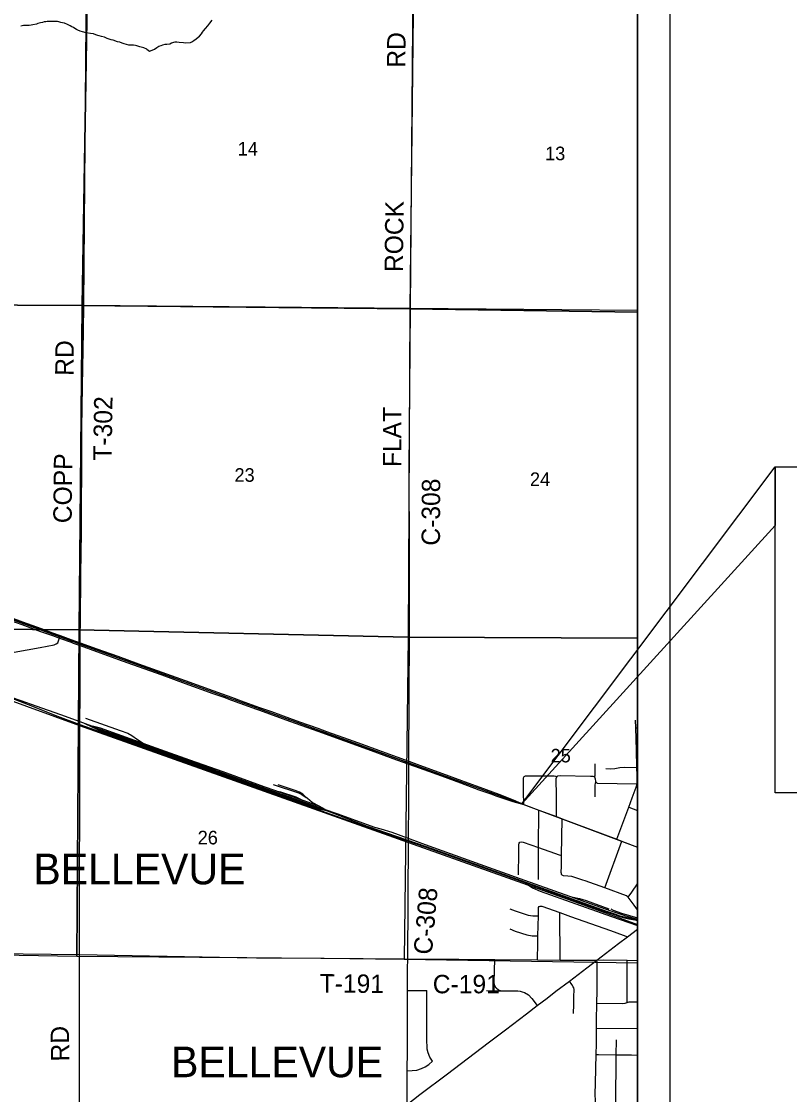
# Model space of a CAD drawing. Extents: x 0 to 34, y 0 to 22.
# Drawn here: x 6.998 to 9.369, y 14.74 to 18.051 of the extents above; entities that cross this region are included whole.
import ezdxf

# ---------------------------------------------------------------- set-up
doc = ezdxf.new("R2010")
doc.units = 0
for name, color, linetype in [('Default', 7, 'Continuous'), ('GM_X_City_Street', 7, 'Continuous'), ('GM_X_Corporation_Text', 7, 'Continuous'), ('GM_X_County_Road', 7, 'Continuous'), ('GM_X_County_Road_Text', 7, 'Continuous'), ('GM_X_Minor_River', 7, 'Continuous'), ('GM_X_Rail_Line', 7, 'Continuous'), ('GM_X_Section', 7, 'Continuous'), ('GM_X_Section_Text', 7, 'Continuous'), ('GM_X_State_Route', 7, 'Continuous'), ('GM_X_Township_Road', 7, 'Continuous'), ('GM_X_Township_Road_Text', 7, 'Continuous'), ('GM_X_US_Route', 7, 'Continuous'), ('SH_Cut_Line', 7, 'Continuous'), ('SH_Data', 7, 'Continuous'), ('SH_Text', 7, 'Continuous')]:
    doc.layers.add(name, color=color, linetype=linetype)

msp = doc.modelspace()

# ---------------------------------------------------------------- linework, layer by layer
at = {"layer": 'Default'}
for points in [[(8.9, 17.1539), (8.9, 18.1619), (8.2084, 18.1673), (8.1974, 17.1648)], [(8.9, 16.1483), (8.9, 17.1539), (8.1974, 17.1648), (8.192, 16.151)], [(8.9, 15.1461), (8.9, 16.1483), (8.192, 16.151), (8.1799, 15.1573)]]:
    msp.add_lwpolyline(points, close=True, dxfattribs=at)
msp.add_lwpolyline([(3.8857, 17.3198), (5.25, 16.8357), (6.6044, 16.3383), (8.5432, 15.6366)], dxfattribs=at)
at = {"layer": 'GM_X_City_Street'}
for p, q in [((8.8943, 15.8713), (8.9, 15.8712)), ((8.8966, 15.8026), (8.9, 15.8026)), ((8.8727, 15.6265), (8.9, 15.6164)), ((8.7988, 15.3772), (8.8517, 15.5218)), ((8.6609, 15.1547), (8.6602, 15.3011)), ((8.8676, 15.0241), (8.8681, 15.1541)), ((8.1903, 15.061), (8.2493, 15.0609)), ((8.7735, 14.9445), (8.9, 14.9432))]:
    msp.add_line(p, q, dxfattribs=at)
for points in [[(8.8358, 15.5278), (8.8727, 15.6265), (8.8832, 15.6557), (8.8956, 15.6887), (8.8992, 15.6989), (8.8986, 15.7256), (8.8978, 15.7492), (8.8966, 15.8026), (8.8943, 15.8713), (8.8933, 15.8951)], [(8.7669, 15.7202), (8.7688, 15.723), (8.7692, 15.7326), (8.7689, 15.7603)], [(8.802, 15.7463), (8.8157, 15.7453), (8.8301, 15.7464), (8.8457, 15.7493), (8.8587, 15.7499), (8.8978, 15.7492)], [(8.5487, 15.6345), (8.5482, 15.6753), (8.5483, 15.7172), (8.5504, 15.7214)], [(8.5504, 15.7214), (8.5537, 15.723), (8.5898, 15.7231), (8.6431, 15.7237), (8.6477, 15.7224), (8.6507, 15.7203)], [(8.7693, 15.6586), (8.7695, 15.6941), (8.7702, 15.7002), (8.772, 15.7032)], [(8.5943, 15.4029), (8.5944, 15.5018), (8.5954, 15.6174)], [(8.5326, 15.4176), (8.5336, 15.4859), (8.5335, 15.5105), (8.5348, 15.5158), (8.5369, 15.5184)], [(8.5369, 15.5184), (8.5409, 15.5195), (8.5474, 15.5183), (8.5944, 15.5018), (8.6438, 15.4841), (8.6578, 15.479), (8.6651, 15.4772)], [(8.871, 15.3489), (8.8824, 15.3647), (8.9, 15.3898)], [(8.5062, 15.3127), (8.5222, 15.3065), (8.5619, 15.2931), (8.5771, 15.291), (8.5939, 15.2908)], [(8.5909, 15.1554), (8.5921, 15.2065), (8.5924, 15.2296), (8.5939, 15.2908), (8.5941, 15.3128), (8.5947, 15.3173), (8.5967, 15.3199)], [(8.5967, 15.3199), (8.5998, 15.3211), (8.6042, 15.3208), (8.6602, 15.3011), (8.6926, 15.2896), (8.8168, 15.2456), (8.856, 15.2318), (8.8691, 15.2263)], [(8.8177, 15.3125), (8.8249, 15.3084), (8.8507, 15.2995), (8.9, 15.2847)], [(8.5062, 15.2512), (8.5227, 15.2443), (8.5582, 15.2321), (8.5743, 15.2297), (8.5924, 15.2296)], [(8.4772, 15.0597), (8.4703, 15.062), (8.4633, 15.0684), (8.4587, 15.0767), (8.4576, 15.0873), (8.4594, 15.1567)], [(8.7026, 14.9897), (8.7028, 15.0178), (8.7029, 15.041), (8.7039, 15.0642), (8.7032, 15.0686), (8.7016, 15.0725), (8.6968, 15.0791), (8.6897, 15.0897)], [(8.2675, 14.8425), (8.259, 14.8546), (8.2533, 14.8681), (8.2502, 14.88), (8.2495, 14.9122), (8.2496, 14.9707), (8.2496, 15.033), (8.2493, 15.0609)], [(8.4338, 15.0603), (8.4654, 15.06), (8.4772, 15.0597), (8.497, 15.0601), (8.5301, 15.0596), (8.5376, 15.0585), (8.5437, 15.0569), (8.5506, 15.0543), (8.5632, 15.0471), (8.5741, 15.0362), (8.5905, 15.0149)], [(8.7747, 15.0214), (8.8547, 15.0203), (8.8619, 15.0216), (8.8676, 15.0241), (8.8741, 15.0256), (8.9, 15.0253)], [(8.8329, 14.7098), (8.8343, 14.8612), (8.8347, 14.9085)], [(8.1893, 14.8132), (8.2038, 14.8136), (8.2184, 14.8152), (8.2333, 14.8197), (8.2446, 14.8254), (8.2557, 14.8328), (8.2675, 14.8425)], [(8.7498, 14.6428), (8.7497, 14.6531), (8.7522, 14.6595), (8.7593, 14.6674), (8.7668, 14.6745), (8.7695, 14.6791), (8.7705, 14.6844), (8.7699, 14.7085), (8.7727, 14.711), (8.7699, 14.7167), (8.7696, 14.7443), (8.7702, 14.7718), (8.7713, 14.8223), (8.7727, 14.8619)]]:
    msp.add_lwpolyline(points, dxfattribs=at)
at = {"layer": 'GM_X_County_Road'}
for p, q in [((8.1954, 16.6674), (8.1995, 17.1669)), ((8.1942, 15.8381), (8.1944, 15.8584)), ((8.1939, 15.7595), (8.1939, 15.7683)), ((8.1939, 15.7497), (8.1939, 15.7595)), ((8.1938, 15.6911), (8.1937, 15.7008)), ((8.1936, 15.6137), (8.1938, 15.6427)), ((8.1912, 15.2255), (8.1913, 15.2351)), ((8.1905, 15.1577), (8.1907, 15.1771)), ((8.1902, 15.1285), (8.1905, 15.1577)), ((8.1905, 15.1577), (8.2102, 15.1577)), ((8.2102, 15.1577), (8.2792, 15.1577)), ((8.3089, 15.1577), (8.3485, 15.1574)), ((8.3485, 15.1574), (8.4376, 15.1568))]:
    msp.add_line(p, q, dxfattribs=at)
for points in [[(8.1995, 17.1669), (8.2077, 18.164), (8.2125, 18.6542), (8.228, 19.2286), (8.2296, 19.6352)], [(8.196, 16.4172), (8.1954, 16.6624), (8.1954, 16.6674)], [(8.1961, 16.2073), (8.1961, 16.2083), (8.1963, 16.2687), (8.196, 16.4122), (8.196, 16.4172)], [(8.1944, 15.8584), (8.1945, 15.8736), (8.1948, 15.9166), (8.1961, 16.2073)], [(8.194, 15.808), (8.1941, 15.8228), (8.1942, 15.8381)], [(8.1939, 15.7683), (8.1939, 15.7872), (8.194, 15.808)], [(8.1937, 15.7008), (8.1937, 15.7027), (8.1939, 15.7497)], [(8.6495, 15.5975), (8.6494, 15.6591), (8.649, 15.7158), (8.6494, 15.7167)], [(8.6494, 15.7167), (8.6507, 15.7203), (8.6542, 15.7228), (8.6616, 15.7238), (8.7546, 15.7225), (8.7618, 15.7218), (8.7649, 15.7208)], [(8.7649, 15.7208), (8.7669, 15.7202), (8.7692, 15.7143), (8.77, 15.7061), (8.772, 15.7032)], [(8.772, 15.7032), (8.7758, 15.701), (8.8992, 15.6989), (8.9, 15.6989)], [(8.1938, 15.6427), (8.1939, 15.6514), (8.1938, 15.6911)], [(8.1929, 15.5364), (8.1932, 15.5596), (8.1936, 15.6127), (8.1936, 15.6137)], [(8.6649, 15.4219), (8.6644, 15.4248), (8.6653, 15.4445), (8.6651, 15.4772), (8.6674, 15.591)], [(8.1926, 15.4977), (8.1926, 15.5064), (8.1929, 15.5364)], [(8.1924, 15.3713), (8.1924, 15.4022), (8.1926, 15.4687)], [(8.1926, 15.4687), (8.1926, 15.4716), (8.1926, 15.4977)], [(8.7381, 15.3989), (8.7316, 15.4013), (8.7062, 15.4099), (8.6973, 15.4126), (8.6852, 15.4138), (8.671, 15.4144), (8.6672, 15.4162), (8.6654, 15.419), (8.6649, 15.4219)], [(8.1921, 15.3324), (8.1924, 15.3616), (8.1924, 15.3713)], [(8.9, 15.3101), (8.8894, 15.3238), (8.871, 15.3489), (8.8658, 15.353), (8.7988, 15.3772), (8.7381, 15.3989)], [(8.1913, 15.2351), (8.1915, 15.2583), (8.1921, 15.3324)], [(8.1907, 15.1771), (8.1909, 15.1984), (8.1912, 15.2255)], [(8.2792, 15.1577), (8.299, 15.1577), (8.3089, 15.1577)], [(8.4376, 15.1568), (8.4594, 15.1567), (8.5909, 15.1554), (8.6609, 15.1547), (8.7747, 15.1546)], [(8.7796, 14.8618), (8.7727, 14.8619), (8.7731, 14.8969), (8.7735, 14.9445), (8.7737, 14.9683), (8.7747, 15.0214), (8.775, 15.0601), (8.7753, 15.1185), (8.7756, 15.1468), (8.7747, 15.1546)], [(8.7747, 15.1546), (8.7953, 15.1552), (8.8681, 15.1541), (8.9, 15.1535)], [(8.1888, 14.7087), (8.1891, 14.766), (8.1893, 14.8132), (8.1894, 14.8752), (8.1898, 14.9491), (8.1903, 15.061), (8.1901, 15.1198), (8.1902, 15.1285)], [(8.9, 14.8605), (8.8813, 14.8607), (8.8343, 14.8612), (8.7796, 14.8618)]]:
    msp.add_lwpolyline(points, dxfattribs=at)
at = {"layer": 'GM_X_Minor_River'}
for points in [[(7.3854, 17.9657), (7.3756, 17.9699), (7.3634, 17.9736), (7.3543, 17.9766), (7.3497, 17.9773), (7.344, 17.9781), (7.338, 17.9784), (7.33, 17.9784), (7.3224, 17.9799), (7.3156, 17.9821), (7.3091, 17.9847), (7.3015, 17.9874), (7.295, 17.9889), (7.2813, 17.9933), (7.2749, 17.9952), (7.2684, 17.9967), (7.2627, 17.9986), (7.2581, 18.0008), (7.254, 18.0027), (7.2448, 18.0049), (7.2384, 18.0072), (7.2338, 18.0083), (7.2281, 18.0106), (7.2205, 18.0128), (7.2114, 18.0143), (7.1981, 18.0169), (7.1863, 18.0199), (7.1795, 18.0217), (7.1722, 18.0244), (7.1681, 18.0262), (7.1627, 18.0296), (7.1585, 18.0326), (7.1536, 18.0353), (7.1483, 18.0375), (7.1403, 18.0421), (7.1311, 18.0466), (7.1251, 18.0473), (7.1201, 18.0488), (7.114, 18.0507), (7.1095, 18.0514), (7.0878, 18.0513), (7.0829, 18.0509), (7.078, 18.0513), (7.0734, 18.0508), (7.0685, 18.0501), (7.0632, 18.0485), (7.0571, 18.047), (7.0488, 18.045), (7.0442, 18.0435), (7.0336, 18.0415), (7.0279, 18.04), (7.0222, 18.0392), (7.0112, 18.0392), (7.0048, 18.0388), (7.0002, 18.0376), (6.996, 18.0368)], [(7.3854, 17.9657), (7.3934, 17.9601), (7.4021, 17.9625), (7.4085, 17.9659), (7.4165, 17.971), (7.4225, 17.9748), (7.4293, 17.9775), (7.4342, 17.9791), (7.4414, 17.9811), (7.4471, 17.9815), (7.4558, 17.9827), (7.4611, 17.9858), (7.4728, 17.989), (7.4774, 17.9887), (7.4846, 17.988), (7.4987, 17.987), (7.5051, 17.9859), (7.5199, 17.9868), (7.5244, 17.9891), (7.5301, 17.9926), (7.5376, 17.998), (7.5437, 18.0034), (7.5482, 18.0065), (7.5538, 18.013), (7.5568, 18.0183), (7.5602, 18.0229), (7.5662, 18.0302), (7.5737, 18.0379), (7.5801, 18.0459), (7.5868, 18.0555)]]:
    msp.add_lwpolyline(points, dxfattribs=at)
at = {"layer": 'GM_X_Rail_Line'}
msp.add_line((7.1916, 15.8857), (7.2173, 15.8762), dxfattribs=at)
for points in [[(2.3438, 17.8832), (3.2394, 17.556), (3.7037, 17.3885), (4.1527, 17.2251), (5.0251, 16.9129), (5.72, 16.6602), (6.7111, 16.2981), (7.2308, 16.1113), (7.9999, 15.8344), (8.5456, 15.6361), (8.9, 15.5035)], [(2.1205, 17.682), (2.6475, 17.5103), (3.1194, 17.3438), (3.8981, 17.0634), (4.4129, 16.8774), (5.5123, 16.484), (6.2938, 16.2008), (7.1773, 15.8785), (7.9469, 15.6046), (8.6994, 15.3378), (8.9, 15.264)], [(6.9289, 15.978), (6.9967, 15.9559), (7.042, 15.9395), (7.1188, 15.9123), (7.1899, 15.8865), (7.2178, 15.8734), (7.2723, 15.8542), (7.4638, 15.785), (7.7247, 15.6929), (7.953, 15.611), (8.0653, 15.5682), (8.2472, 15.5053), (8.4865, 15.4197), (8.8012, 15.3067), (8.8315, 15.296), (8.8453, 15.2914), (8.8602, 15.2877), (8.8738, 15.2847), (8.8918, 15.2814), (8.9, 15.2794)], [(6.9385, 15.9745), (7.0187, 15.9431), (7.1093, 15.9079), (7.1781, 15.8821), (7.4621, 15.7808), (7.7222, 15.6881), (7.9506, 15.6064), (8.0645, 15.566), (8.2465, 15.5031), (8.4857, 15.4176), (8.8004, 15.3045), (8.8308, 15.2938), (8.8446, 15.2892), (8.8596, 15.2854), (8.8733, 15.2824), (8.8913, 15.2791), (8.9, 15.277)], [(7.1961, 15.9014), (7.3033, 15.8632), (7.3263, 15.855), (7.3388, 15.8481), (7.3564, 15.8353), (7.3767, 15.8224)], [(7.7799, 15.6779), (7.7471, 15.6895), (7.6213, 15.7352), (7.5174, 15.7719), (7.4284, 15.804), (7.2931, 15.8521), (7.2418, 15.8705), (7.2173, 15.8762)], [(7.2173, 15.8762), (7.2381, 15.8686), (7.4156, 15.8053), (7.5936, 15.7414), (7.7497, 15.6854), (7.8984, 15.6327), (7.9357, 15.6197)], [(7.2178, 15.8734), (7.245, 15.8616), (7.4633, 15.7832), (7.7239, 15.6907), (7.9165, 15.6216), (7.9351, 15.6175)], [(7.7753, 15.6966), (7.853, 15.6711), (7.8632, 15.6661), (7.8775, 15.6566)], [(7.8679, 15.647), (7.8476, 15.6541), (7.7799, 15.6779)], [(7.7799, 15.6779), (7.7975, 15.674), (7.8448, 15.6586), (7.8679, 15.647)], [(7.8775, 15.6566), (7.8667, 15.6663), (7.8564, 15.6726), (7.8434, 15.6778), (7.7911, 15.6954)], [(7.9357, 15.6197), (7.9167, 15.6296), (7.8966, 15.637), (7.8679, 15.647)], [(7.9167, 15.6296), (7.896, 15.6406), (7.8812, 15.6533), (7.8775, 15.6566)], [(7.9357, 15.6197), (7.9722, 15.607), (8.0879, 15.565), (8.1078, 15.5596), (8.1417, 15.5489), (8.2441, 15.5112), (8.4132, 15.451), (8.5362, 15.4063), (8.6902, 15.3515), (8.8177, 15.3061), (8.8639, 15.2909), (8.9, 15.2804)], [(8.5535, 15.3932), (8.5762, 15.3773), (8.5992, 15.3677), (8.8194, 15.2888), (8.9, 15.2615)], [(8.6963, 15.3493), (8.721, 15.3445), (8.7412, 15.3387), (8.8118, 15.3127)]]:
    msp.add_lwpolyline(points, dxfattribs=at)
at = {"layer": 'GM_X_Section'}
for points in [[(7.2022, 18.181), (7.1859, 17.1752), (6.185, 17.1797), (6.1951, 18.1802)], [(7.2022, 18.181), (8.2084, 18.1673), (8.1974, 17.1648), (7.1859, 17.1752)], [(6.185, 17.1797), (7.1859, 17.1752), (7.1762, 16.1739), (6.1703, 16.1807)], [(7.1859, 17.1752), (8.1974, 17.1648), (8.192, 16.151), (7.1762, 16.1739)], [(7.1762, 16.1739), (7.1686, 15.1654), (6.1617, 15.1831), (6.1703, 16.1807)], [(7.1762, 16.1739), (8.192, 16.151), (8.1799, 15.1573), (7.1686, 15.1654)]]:
    msp.add_lwpolyline(points, close=True, dxfattribs=at)
at = {"layer": 'GM_X_State_Route'}
for points in [[(8.4389, 14.8988), (8.4921, 14.9393), (8.5567, 14.9885), (8.5905, 15.0149), (8.6213, 15.0375), (8.6479, 15.0583), (8.6897, 15.0897), (8.7433, 15.1306), (8.7747, 15.1546), (8.8415, 15.2053), (8.8691, 15.2263), (8.9, 15.2499)], [(8.1888, 14.7087), (8.2284, 14.7395), (8.3137, 14.8036), (8.4389, 14.8988)]]:
    msp.add_lwpolyline(points, dxfattribs=at)
at = {"layer": 'GM_X_Township_Road'}
for p, q in [((7.1893, 17.0957), (7.1906, 17.1758)), ((7.1906, 17.1758), (8.1995, 17.1669)), ((8.1995, 17.1669), (8.9, 17.1603)), ((7.1867, 16.9254), (7.1893, 17.0957)), ((7.1845, 16.7554), (7.185, 16.7952)), ((7.181, 16.2738), (7.1817, 16.3443)), ((7.1796, 16.1251), (7.1795, 16.1339)), ((6.9162, 16.094), (7.0561, 16.1195)), ((7.0561, 16.1195), (7.0991, 16.1273)), ((7.1794, 16.115), (7.1796, 16.1251)), ((7.1768, 15.1715), (7.6637, 15.1627)), ((7.6935, 15.1622), (7.7233, 15.1619)), ((7.7233, 15.1619), (7.9221, 15.1601)), ((7.9221, 15.1601), (7.9321, 15.1601)), ((7.9321, 15.1601), (8.0116, 15.1593)), ((8.0116, 15.1593), (8.0911, 15.1586)), ((8.0911, 15.1586), (8.111, 15.1585)), ((8.111, 15.1585), (8.1905, 15.1577))]:
    msp.add_line(p, q, dxfattribs=at)
for points in [[(8.9, 14.1483), (8.9, 20.2053), (7.2271, 20.2132), (6.4763, 20.2191), (6.0936, 20.222), (5.2207, 20.2288), (4.224, 20.2365), (3.2241, 20.2443), (3.2118, 19.2455), (3.2116, 19.2346), (3.2069, 18.535), (3.1896, 17.5787), (3.1895, 17.5705), (3.1894, 17.563), (3.1774, 16.6219), (3.1774, 16.6199), (3.1628, 15.2158), (3.1576, 14.794), (3.1491, 14.2171)], [(7.1906, 17.1758), (7.1989, 18.1769), (7.2124, 19.0336)], [(5.1865, 17.1917), (5.3114, 17.1916), (5.4642, 17.1891), (5.9368, 17.1818), (5.9591, 17.1811), (6.1898, 17.1786), (6.6892, 17.1776), (7.1906, 17.1758)], [(7.185, 16.7952), (7.185, 16.7961), (7.1867, 16.9254)], [(7.1831, 16.4746), (7.1845, 16.7514), (7.1845, 16.7554)], [(7.1824, 16.4147), (7.1831, 16.4716), (7.1831, 16.4746)], [(7.1817, 16.3443), (7.1818, 16.3453), (7.1823, 16.4097), (7.1824, 16.4147)], [(7.1799, 16.2044), (7.1799, 16.2075), (7.1809, 16.2698), (7.181, 16.2738)], [(7.1795, 16.1339), (7.1794, 16.1521), (7.1799, 16.2044)], [(7.0991, 16.1273), (7.1053, 16.1302), (7.11, 16.1341), (7.1129, 16.1394), (7.1138, 16.1427)], [(7.1138, 16.1427), (7.1152, 16.1482), (7.1174, 16.1564)], [(7.1791, 16.056), (7.1794, 16.111), (7.1794, 16.115)], [(7.1785, 15.8994), (7.1791, 15.9623), (7.1791, 16.054), (7.1791, 16.056)], [(7.1782, 15.8692), (7.1785, 15.8964), (7.1785, 15.8994)], [(7.177, 14.168), (7.1768, 15.1715), (7.1782, 15.8682), (7.1782, 15.8692)], [(6.1703, 15.1871), (6.1806, 15.1847), (6.196, 15.1833), (6.2197, 15.1828), (7.1768, 15.1715)], [(7.6637, 15.1627), (7.6896, 15.1622), (7.6935, 15.1622)]]:
    msp.add_lwpolyline(points, dxfattribs=at)
at = {"layer": 'GM_X_US_Route'}
msp.add_line((8.8536, 15.5211), (8.9, 15.5035), dxfattribs=at)
for points in [[(6.7032, 16.2977), (6.7277, 16.2888), (6.807, 16.2601), (6.9001, 16.2262), (6.9296, 16.2157), (6.9639, 16.2031), (6.9996, 16.1902), (7.0573, 16.1692), (7.0939, 16.1559), (7.1152, 16.1482), (7.1512, 16.1353), (7.1578, 16.133)], [(6.9325, 16.2234), (6.9655, 16.2117), (7.0012, 16.1987), (7.0586, 16.1778), (7.0943, 16.1649), (7.1174, 16.1564)], [(7.1174, 16.1564), (7.1508, 16.1444), (7.1795, 16.1339)], [(7.1578, 16.133), (7.1796, 16.1251), (7.2299, 16.1069), (7.2898, 16.0854)], [(7.1795, 16.1339), (7.2312, 16.1154), (7.2958, 16.0921), (7.359, 16.0693), (7.431, 16.0433), (7.5034, 16.0174), (7.5892, 15.9865), (7.6466, 15.9658), (7.6762, 15.9551), (7.7332, 15.9345), (7.7697, 15.9214), (7.826, 15.9011), (7.8561, 15.8901), (7.9126, 15.87), (7.9399, 15.86), (7.9927, 15.8411), (8.0495, 15.8205), (8.0999, 15.8024), (8.1566, 15.782), (8.1939, 15.7683)], [(7.2898, 16.0854), (7.2944, 16.0837), (7.3588, 16.0606), (7.431, 16.0345), (7.5034, 16.0086), (7.5892, 15.9777), (7.6225, 15.9657)], [(7.6225, 15.9657), (7.6466, 15.957), (7.724, 15.9291)], [(7.724, 15.9291), (7.7332, 15.9257), (7.826, 15.8923), (7.9126, 15.8612), (7.9953, 15.8311), (8.0779, 15.8015), (8.1563, 15.773), (8.1939, 15.7595), (8.24, 15.7427), (8.2945, 15.7228), (8.353, 15.7014), (8.4103, 15.6805), (8.4473, 15.6672)], [(8.1939, 15.7683), (8.2187, 15.7593), (8.2498, 15.7479), (8.2979, 15.7303), (8.3569, 15.7088), (8.4129, 15.688), (8.4713, 15.6667), (8.5159, 15.6494), (8.5487, 15.6345)], [(8.4473, 15.6672), (8.4654, 15.6606), (8.5147, 15.6438), (8.5487, 15.6345), (8.5954, 15.6174), (8.6495, 15.5975), (8.6674, 15.591), (8.8358, 15.5278), (8.8517, 15.5218), (8.8536, 15.5211)]]:
    msp.add_lwpolyline(points, dxfattribs=at)
at = {"layer": 'SH_Cut_Line'}
msp.add_lwpolyline([(8.9, 14.1483), (8.9, 20.9), (2.1, 20.9), (2.1, 14.2219)], dxfattribs=at)
at = {"layer": 'SH_Data'}
for p, q in [((9, 21), (9, 14)), ((8.9, 20.9), (8.9, 14.1))]:
    msp.add_line(p, q, dxfattribs=at)
at = {"layer": 'SH_Text'}
for points in [[(8.5432, 15.6366), (9.3253, 16.6766), (9.3253, 16.496)], [(9.3253, 16.6766), (12.6165, 16.6766), (12.6165, 15.6711), (9.3253, 15.6711)]]:
    msp.add_lwpolyline(points, close=True, dxfattribs=at)

# ---------------------------------------------------------------- texts
at = {"layer": 'GM_X_Corporation_Text'}
for p in [(7.0349, 15.3886), (7.0349, 15.3884), (7.035, 15.3886), (7.46, 14.793)]:
    msp.add_text('BELLEVUE', height=0.0947, rotation=0, dxfattribs=at).set_placement(p)
at = {"layer": 'GM_X_County_Road_Text'}
for s, rotation, p in [('RD', 89.5063, (8.1831, 17.9085)), ('ROCK', 89.2901, (8.1756, 17.2777)), ('FLAT', 89.7247, (8.1705, 16.6759)), ('C-308', 89.7247, (8.29, 16.4336)), ('C-308', 85.0338, (8.265, 15.1698)), ('C-191', 0, (8.2679, 15.0521))]:
    msp.add_text(s, height=0.05682, rotation=rotation, dxfattribs=at).set_placement(p)
at = {"layer": 'GM_X_Section_Text'}
for s, p in [('14', (7.6658, 17.6378)), ('13', (8.6146, 17.6233)), ('23', (7.6558, 16.6308)), ('24', (8.5679, 16.6178)), ('25', (8.6317, 15.7646)), ('26', (7.5421, 15.5117))]:
    msp.add_text(s, height=0.04186, rotation=0, dxfattribs=at).set_placement(p)
at = {"layer": 'GM_X_Township_Road_Text'}
for s, rotation, p in [('RD', 89.5063, (7.1589, 16.9576)), ('T-302', 89.1659, (7.2765, 16.6957)), ('COPP', 89.4494, (7.1531, 16.5027)), ('T-191', 359.4474, (7.9186, 15.0547)), ('RD', 90.9891, (7.1464, 14.8421))]:
    msp.add_text(s, height=0.05682, rotation=rotation, dxfattribs=at).set_placement(p)

doc.saveas('drawing.dxf')
